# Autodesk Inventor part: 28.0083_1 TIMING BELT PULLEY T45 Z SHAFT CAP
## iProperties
Created: 2007-06
Part Number: 28.0083_1 TIMING BELT PULLEY T45 Z SHAFT CAP
Material: Steel
Document SubType Name: Modeling
Designer: Andy Moles
Mass: 5.56668 g
Surface Area: 7.23077 cm^2
Volume: 0.709131 cm^3
Density: 7.85 g/cm^3
Author: Andy Moles
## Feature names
1. Extrusion1
2. Chamfer1
